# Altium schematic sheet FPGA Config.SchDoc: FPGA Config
size B; Date: 12/18/2013; DrawnBy: David McCoy; Engineer: David McCoy (Cospan Design); DocumentNumber: 4; Revision: C; SheetNumber: 4; SheetTotal: 10
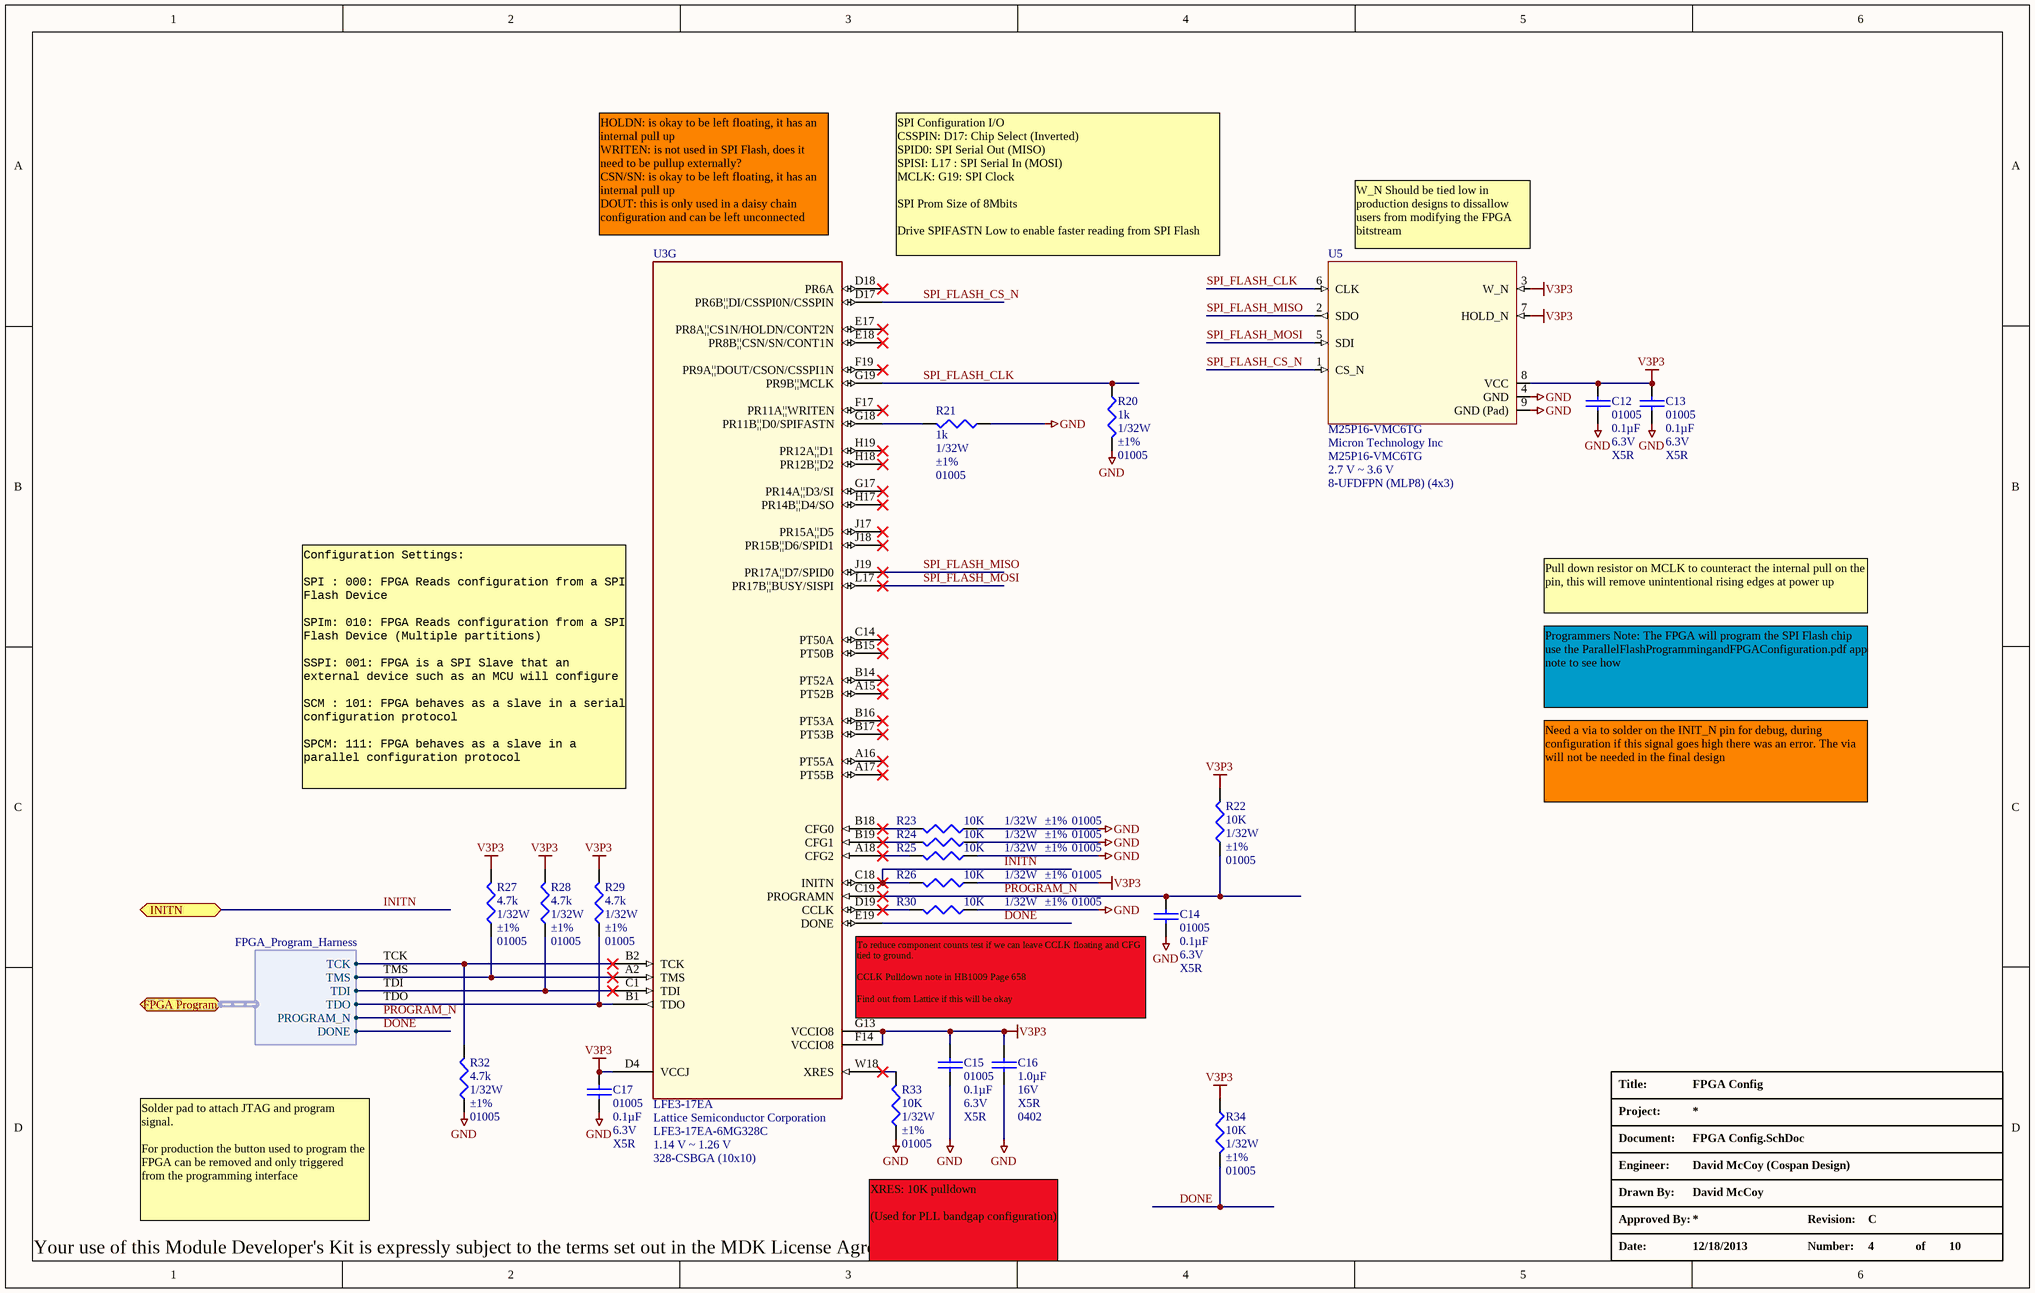
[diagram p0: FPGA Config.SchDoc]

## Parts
C12  Package / Case: 01005  Capacitance: 0.1µF  Voltage - Rated: 6.3V  Temperature Coefficient: X5R  [C_01005]  (hidden comment: 0.1uF)
C13  Package / Case: 01005  Capacitance: 0.1µF  Voltage - Rated: 6.3V  Temperature Coefficient: X5R  [C_01005]  (hidden comment: 0.1uF)
C14  Package / Case: 01005  Capacitance: 0.1µF  Voltage - Rated: 6.3V  Temperature Coefficient: X5R  [C_01005]  (hidden comment: 0.1uF)
C15  Package / Case: 01005  Capacitance: 0.1µF  Voltage - Rated: 6.3V  Temperature Coefficient: X5R  [C_01005]  (hidden comment: 0.1uF)
C16  Capacitance: 1.0µF  Voltage - Rated: 16V  Temperature Coefficient: X5R  Package / Case: 0402  [C_ERA-0402]  (hidden comment: 1.0uF)
C17  Package / Case: 01005  Capacitance: 0.1µF  Voltage - Rated: 6.3V  Temperature Coefficient: X5R  [C_01005]  (hidden comment: 0.1uF)
R20  Power (Watts): 1/32W  Tolerance: ±1%  Case: 01005  [R_01005]  (hidden comment: 1k)
R21  Power (Watts): 1/32W  Tolerance: ±1%  Case: 01005  [R_01005]  (hidden comment: 1k)
R22  Power (Watts): 1/32W  Tolerance: ±1%  Case: 01005  [R_01005]  (hidden comment: 10K)
R23  Power (Watts): 1/32W  Tolerance: ±1%  Case: 01005  [R_01005]  (hidden comment: 10K)
R24  Power (Watts): 1/32W  Tolerance: ±1%  Case: 01005  [R_01005]  (hidden comment: 10K)
R25  Power (Watts): 1/32W  Tolerance: ±1%  Case: 01005  [R_01005]  (hidden comment: 10K)
R26  Power (Watts): 1/32W  Tolerance: ±1%  Case: 01005  [R_01005]  (hidden comment: 10K)
R27  Power (Watts): 1/32W  Tolerance: ±1%  Case: 01005  [R_01005]  (hidden comment: 4.7k)
R28  Power (Watts): 1/32W  Tolerance: ±1%  Case: 01005  [R_01005]  (hidden comment: 4.7k)
R29  Power (Watts): 1/32W  Tolerance: ±1%  Case: 01005  [R_01005]  (hidden comment: 4.7k)
R30  Power (Watts): 1/32W  Tolerance: ±1%  Case: 01005  [R_01005]  (hidden comment: 10K)
R32  Power (Watts): 1/32W  Tolerance: ±1%  Case: 01005  [R_01005]  (hidden comment: 4.7k)
R33  Power (Watts): 1/32W  Tolerance: ±1%  Case: 01005  [R_01005]  (hidden comment: 10K)
R34  Power (Watts): 1/32W  Tolerance: ±1%  Case: 01005  [R_01005]  (hidden comment: 10K)
U3  LFE3-17EA  Manufacturer: Lattice Semiconductor Corporation  Manufacturer Part Number: LFE3-17EA-6MG328C  Voltage - Supply: 1.14 V ~ 1.26 V  Supplier Device Package: 328-CSBGA (10x10)  [BGA328C50P19X19_1000X1000X150]  (part G of 10)
U5  M25P16-VMC6TG  Manufacturer: Micron Technology Inc  Voltage - Supply: 2.7 V ~ 3.6 V  Supplier Device Package: 8-UFDFPN (MLP8) (4x3)  [UFDFN8]

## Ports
FPGA Program (harness FPGA_Program_Harness), INITN

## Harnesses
FPGA_Program_Harness: TCK, TMS, TDI, TDO, PROGRAM_N, DONE

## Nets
GND: C12.2 C13.2 C14.2 C15.2 C16.1 C17.2 R20.1 R21.2 R23.2 R24.2 R25.2 R30.2 R32.2 R33.2 U5.4(GND) U5.9(GND_(Pad))
V3P3: C12.1 C13.1 C15.1 C16.2 C17.1 R22.1 R26.2 R27.1 R28.1 R29.1 R34.2 U3.D4(VCCJ) U3.F14(VCCIO8) U3.G13(VCCIO8) U5.3(W_N) U5.7(HOLD_N) U5.8(VCC)
DONE: R34.1 U3.E19(DONE) ; port FPGA Program.DONE
INITN: R26.1 U3.C18(INITN) ; port INITN
PROGRAM_N: C14.1 R22.2 U3.C19(PROGRAMN) ; port FPGA Program.PROGRAM_N
SPI_FLASH_CLK: R20.2 U3.G19(PR9B¦¦MCLK) U5.6(CLK)
SPI_FLASH_CS_N: U3.D17(PR6B¦¦DI/CSSPI0N/CSSPIN) U5.1(CS_N)
SPI_FLASH_MISO: U3.J19(PR17A¦¦D7/SPID0) U5.2(SDO)
SPI_FLASH_MOSI: U3.L17(PR17B¦¦BUSY/SISPI) U5.5(SDI)
TCK: R32.1 U3.B2(TCK) ; port FPGA Program.TCK
TDI: R28.2 U3.C1(TDI) ; port FPGA Program.TDI
TDO: R29.2 U3.B1(TDO) ; port FPGA Program.TDO
TMS: R27.2 U3.A2(TMS) ; port FPGA Program.TMS
NetR21_1: R21.1 U3.G18(PR11B¦¦D0/SPIFASTN)
NetR23_1: R23.1 U3.B18(CFG0)
NetR24_1: R24.1 U3.B19(CFG1)
NetR25_1: R25.1 U3.A18(CFG2)
NetR30_1: R30.1 U3.D19(CCLK)
NetR33_1: R33.1 U3.W18(XRES)

Not connected (* = marked no-connect by the designer): U3 A15(PT52B)* A16(PT55A)* A17(PT55B)* B14(PT52A)* B15(PT50B)* B16(PT53A)* B17(PT53B)* C14(PT50A)* D18(PR6A)* E17(PR8A¦¦CS1N/HOLDN/CONT2N)* E18(PR8B¦¦CSN/SN/CONT1N)* F17(PR11A¦¦WRITEN)* F19(PR9A¦¦DOUT/CSON/CSSPI1N)* G17(PR14A¦¦D3/SI)* H17(PR14B¦¦D4/SO)* H18(PR12B¦¦D2)* H19(PR12A¦¦D1)* J17(PR15A¦¦D5)* J18(PR15B¦¦D6/SPID1)*

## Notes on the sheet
- HOLDN: is okay to be left floating, it has an internal pull up
  WRITEN: is not used in SPI Flash, does it need to be pullup externally?
  CSN/SN: is okay to be left floating, it has an internal pull up
  DOUT: this is only used in a daisy chain configuration and can be left unconnected
- SPI Configuration I/O
  CSSPIN: D17: Chip Select (Inverted)
  SPID0: SPI Serial Out (MISO)
  SPISI: L17 : SPI Serial In (MOSI)
  MCLK: G19: SPI Clock
  SPI Prom Size of 8Mbits
  Drive SPIFASTN Low to enable faster reading from SPI Flash
- (near U5) W_N Should be tied low in production designs to dissallow users from modifying the FPGA bitstream
- Pull down resistor on MCLK to counteract the internal pull on the pin, this will remove unintentional rising edges at power up
- Programmers Note: The FPGA will program the SPI Flash chip use the ParallelFlashProgrammingandFPGAConfiguration.pdf app note to see how
- (near U3) Configuration Settings:
  SPI : 000: FPGA Reads configuration from a SPI Flash Device
  SPIm: 010: FPGA Reads configuration from a SPI Flash Device (Multiple partitions)
  SSPI: 001: FPGA is a SPI Slave that an external device such as an MCU will configure
  SCM : 101: FPGA behaves as a slave in a serial configuration protocol
  SPCM: 111: FPGA behaves as a slave in a parallel configuration protocol
- Need a via to solder on the INIT_N pin for debug, during configuration if this signal goes high there was an error. The via will not be needed in the final design
- (near U3) To reduce component counts test if we can leave CCLK floating and CFG tied to ground.
  CCLK Pulldown note in HB1009 Page 658
  Find out from Lattice if this will be okay
- Solder pad to attach JTAG and program signal.
  For production the button used to program the FPGA can be removed and only triggered from the programming interface
- XRES: 10K pulldown
  (Used for PLL bandgap configuration)

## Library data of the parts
C12-C15 C17 = C_01005_0.1uF: CAP CER 0.1UF 6.3V 20% X5R 01005; Manufacturer: TDK Corporation; Manufacturer Part Number: C0402X5R0J104M020BC
C16 = C_0402_1.0UF_16V: CAP CER 1.0UF 16V X5R 0402; Manufacturer: TDK Corporation; Manufacturer Part Number: C1005X5R1C105K; Tolerance: ±10%
R20 R21 = R_01005_1k: RES 1K OHM 1/32W 1% 01005 SM; Manufacturer: Panasonic Electronic Components; Manufacturer Part Number: ERJ-XGNF1001Y; Temperature Coefficient: ±200ppm/°C
R22-R26 R30 R33 R34 = R_01005_10K: RES 10K OHM 1/32W 1% 01005; Manufacturer: Samsung Electro-Mechanics America, Inc; Manufacturer Part Number: RC0402F103CS; Temperature Coefficient: ±250ppm/°C
R27-R29 R32 = R_01005_4.7k: RES 4.7K OHM 1/32W 1% 01005 SMD; Manufacturer: Yageo; Manufacturer Part Number: RC0100FR-074K7L; Temperature Coefficient: ±250ppm/°C
U3 = U_LFE3-17EA-MG328: IC FPGA 17KLUTS 116I/O 328-BGA; SPLIT_INST: TRUE; SWAP_INFO: (S1+S2+S3+S4+S5+S6+S7+S8+S9+S10); Number of LABs/CLBs: 2125; Number of Logic Elements/Cells: 17000; Total RAM Bits: 716800; Number of I /O: 116
U5 = U_M25P16-VMC6TG: IC FLASH 16MBIT 75MHZ 8UFDFPN; Memory Type: FLASH - NOR; Memory Size: 16M (2M x 8); Interface: SPI Serial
